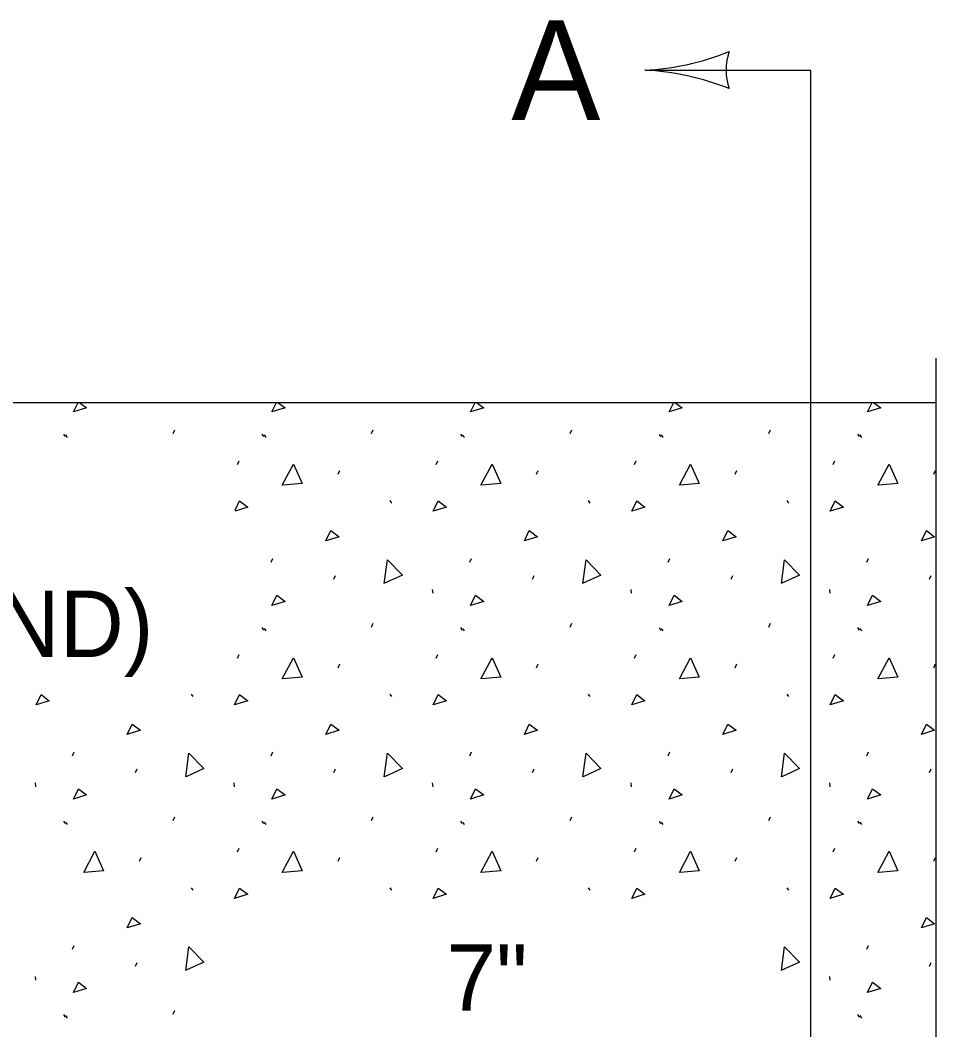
# Model space of a CAD drawing. Extents: x 49991.4 to 50021, y 49987.6 to 50011.4.
# Drawn here: x 50006.829 to 50007.655, y 49991.76 to 49992.672 of the extents above; entities that cross this region are included whole.
import ezdxf

# ---------------------------------------------------------------- set-up
doc = ezdxf.new("R2010")
doc.units = 0
for name, color, linetype in [('Level 1', 7, 'Continuous'), ('Level 2', 7, 'Continuous'), ('Level 3', 7, 'Continuous'), ('Level 6', 7, 'Continuous')]:
    doc.layers.add(name, color=color, linetype=linetype)

msp = doc.modelspace()

# ---------------------------------------------------------------- linework, layer by layer
at = {"layer": 'Level 1'}
for p, q in [((50005.32721, 49992.32693), (50007.65502, 49992.32693)), ((50006.87687, 49992.31824), (50006.88104, 49992.32693)), ((50007.05602, 49992.31824), (50007.0602, 49992.32693)), ((50007.23518, 49992.31824), (50007.23935, 49992.32693)), ((50007.41434, 49992.31824), (50007.41851, 49992.32693)), ((50007.5935, 49992.31824), (50007.59767, 49992.32693)), ((50006.86778, 49992.29835), (50006.86927, 49992.29611)), ((50006.86977, 49992.29749), (50006.87127, 49992.29526)), ((50006.96675, 49992.29885), (50006.96824, 49992.3022)), ((50007.04694, 49992.29835), (50007.04843, 49992.29611)), ((50007.04893, 49992.29749), (50007.05043, 49992.29526)), ((50007.14591, 49992.29885), (50007.1474, 49992.3022)), ((50007.2261, 49992.29835), (50007.22759, 49992.29611)), ((50007.22809, 49992.29749), (50007.22958, 49992.29526)), ((50007.32507, 49992.29885), (50007.32656, 49992.3022)), ((50007.40526, 49992.29835), (50007.40675, 49992.29611)), ((50007.40725, 49992.29749), (50007.40874, 49992.29526)), ((50007.50423, 49992.29885), (50007.50572, 49992.3022)), ((50007.58442, 49992.29835), (50007.58591, 49992.29611)), ((50007.58641, 49992.29749), (50007.5879, 49992.29526)), ((50007.02493, 49992.2707), (50007.02642, 49992.27405)), ((50007.20409, 49992.2707), (50007.20558, 49992.27405)), ((50007.38325, 49992.2707), (50007.38474, 49992.27405)), ((50007.56241, 49992.2707), (50007.5639, 49992.27405)), ((50007.1157, 49992.26212), (50007.11719, 49992.26548)), ((50007.29486, 49992.26212), (50007.29635, 49992.26548)), ((50007.47401, 49992.26212), (50007.47551, 49992.26548)), ((50007.65317, 49992.26212), (50007.65467, 49992.26548)), ((50007.02276, 49992.22947), (50007.0268, 49992.23788)), ((50007.03426, 49992.23228), (50007.02276, 49992.22869)), ((50007.0268, 49992.23788), (50007.03426, 49992.23228)), ((50007.16232, 49992.23825), (50007.16381, 49992.23601)), ((50007.20148, 49992.22855), (50007.20596, 49992.23788)), ((50007.21342, 49992.23228), (50007.20148, 49992.22855)), ((50007.20596, 49992.23788), (50007.21342, 49992.23228)), ((50007.34148, 49992.23825), (50007.34297, 49992.23601)), ((50007.38064, 49992.22855), (50007.38512, 49992.23788)), ((50007.39257, 49992.23228), (50007.38064, 49992.22855)), ((50007.38512, 49992.23788), (50007.39257, 49992.23228)), ((50007.52064, 49992.23825), (50007.52213, 49992.23601)), ((50007.5598, 49992.22855), (50007.56427, 49992.23788)), ((50007.57173, 49992.23228), (50007.5598, 49992.22855)), ((50007.56427, 49992.23788), (50007.57173, 49992.23228)), ((50007.05528, 49992.18268), (50007.05677, 49992.18604)), ((50007.23444, 49992.18268), (50007.23593, 49992.18604)), ((50007.41359, 49992.18268), (50007.41509, 49992.18604)), ((50007.59275, 49992.18268), (50007.59425, 49992.18604)), ((50007.11197, 49992.16739), (50007.11346, 49992.17074)), ((50007.29113, 49992.16739), (50007.29262, 49992.17074)), ((50007.47029, 49992.16739), (50007.47178, 49992.17074)), ((50007.64944, 49992.16739), (50007.65094, 49992.17074)), ((50007.20064, 49992.15802), (50007.20102, 49992.15466)), ((50007.3798, 49992.15802), (50007.38018, 49992.15466)), ((50007.55896, 49992.15802), (50007.55933, 49992.15466)), ((50007.04694, 49992.12362), (50007.04843, 49992.12139)), ((50007.04893, 49992.12277), (50007.05043, 49992.12054)), ((50007.14591, 49992.12412), (50007.1474, 49992.12748)), ((50007.2261, 49992.12362), (50007.22759, 49992.12139)), ((50007.22809, 49992.12277), (50007.22958, 49992.12054)), ((50007.32507, 49992.12412), (50007.32656, 49992.12748)), ((50007.40526, 49992.12362), (50007.40675, 49992.12139)), ((50007.40725, 49992.12277), (50007.40874, 49992.12054)), ((50007.50423, 49992.12412), (50007.50572, 49992.12748)), ((50007.58442, 49992.12362), (50007.58591, 49992.12139)), ((50007.58641, 49992.12277), (50007.5879, 49992.12054)), ((50007.02493, 49992.09598), (50007.02642, 49992.09933)), ((50007.20409, 49992.09598), (50007.20558, 49992.09933)), ((50007.38325, 49992.09598), (50007.38474, 49992.09933)), ((50007.56241, 49992.09598), (50007.5639, 49992.09933)), ((50007.1157, 49992.0874), (50007.11719, 49992.09076)), ((50007.29486, 49992.0874), (50007.29635, 49992.09076)), ((50007.47401, 49992.0874), (50007.47551, 49992.09076)), ((50007.65317, 49992.0874), (50007.65467, 49992.09076)), ((50006.84316, 49992.05383), (50006.84764, 49992.06316)), ((50006.8551, 49992.05756), (50006.84316, 49992.05383)), ((50006.84764, 49992.06316), (50006.8551, 49992.05756)), ((50006.98316, 49992.06353), (50006.98465, 49992.06129)), ((50007.02232, 49992.05383), (50007.0268, 49992.06316)), ((50007.03426, 49992.05756), (50007.02232, 49992.05383)), ((50007.0268, 49992.06316), (50007.03426, 49992.05756)), ((50007.16232, 49992.06353), (50007.16381, 49992.06129)), ((50007.20148, 49992.05383), (50007.20596, 49992.06316)), ((50007.21342, 49992.05756), (50007.20148, 49992.05383)), ((50007.20596, 49992.06316), (50007.21342, 49992.05756)), ((50007.34148, 49992.06353), (50007.34297, 49992.06129)), ((50007.38064, 49992.05383), (50007.38512, 49992.06316)), ((50007.39257, 49992.05756), (50007.38064, 49992.05383)), ((50007.38512, 49992.06316), (50007.39257, 49992.05756)), ((50007.52064, 49992.06353), (50007.52213, 49992.06129)), ((50007.5598, 49992.05383), (50007.56427, 49992.06316)), ((50007.57173, 49992.05756), (50007.5598, 49992.05383)), ((50007.56427, 49992.06316), (50007.57173, 49992.05756)), ((50006.87612, 49992.00796), (50006.87761, 49992.01131)), ((50007.05528, 49992.00796), (50007.05677, 49992.01131)), ((50007.23444, 49992.00796), (50007.23593, 49992.01131)), ((50007.41359, 49992.00796), (50007.41509, 49992.01131)), ((50007.59275, 49992.00796), (50007.59425, 49992.01131)), ((50006.93281, 49991.99266), (50006.9343, 49991.99602)), ((50007.11197, 49991.99266), (50007.11346, 49991.99602)), ((50007.29113, 49991.99266), (50007.29262, 49991.99602)), ((50007.47029, 49991.99266), (50007.47178, 49991.99602)), ((50007.64944, 49991.99266), (50007.65094, 49991.99602)), ((50006.84232, 49991.9833), (50006.8427, 49991.97994)), ((50007.02148, 49991.9833), (50007.02186, 49991.97994)), ((50007.20064, 49991.9833), (50007.20102, 49991.97994)), ((50007.3798, 49991.9833), (50007.38018, 49991.97994)), ((50007.55896, 49991.9833), (50007.55933, 49991.97994)), ((50006.86778, 49991.9489), (50006.86927, 49991.94666)), ((50006.86977, 49991.94805), (50006.87127, 49991.94581)), ((50006.96675, 49991.9494), (50006.96824, 49991.95276)), ((50007.04694, 49991.9489), (50007.04843, 49991.94666)), ((50007.04893, 49991.94805), (50007.05043, 49991.94581)), ((50007.14591, 49991.9494), (50007.1474, 49991.95276)), ((50007.2261, 49991.9489), (50007.22759, 49991.94666)), ((50007.22809, 49991.94805), (50007.22958, 49991.94581)), ((50007.32507, 49991.9494), (50007.32656, 49991.95276)), ((50007.40526, 49991.9489), (50007.40675, 49991.94666)), ((50007.40725, 49991.94805), (50007.40874, 49991.94581)), ((50007.50423, 49991.9494), (50007.50572, 49991.95276)), ((50007.58442, 49991.9489), (50007.58591, 49991.94666)), ((50007.58641, 49991.94805), (50007.5879, 49991.94581)), ((50007.02493, 49991.92125), (50007.02642, 49991.92461)), ((50007.20409, 49991.92125), (50007.20558, 49991.92461)), ((50007.38325, 49991.92125), (50007.38474, 49991.92461)), ((50007.56241, 49991.92125), (50007.5639, 49991.92461)), ((50006.93654, 49991.91268), (50006.93803, 49991.91603)), ((50007.1157, 49991.91268), (50007.11719, 49991.91603)), ((50007.29486, 49991.91268), (50007.29635, 49991.91603)), ((50007.47401, 49991.91268), (50007.47551, 49991.91603)), ((50007.65317, 49991.91268), (50007.65467, 49991.91603)), ((50006.98316, 49991.88881), (50006.98465, 49991.88657)), ((50007.02232, 49991.87911), (50007.0268, 49991.88843)), ((50007.0268, 49991.88843), (50007.03426, 49991.88284)), ((50007.16232, 49991.88881), (50007.16381, 49991.88657)), ((50007.20148, 49991.87911), (50007.20596, 49991.88843)), ((50007.20596, 49991.88843), (50007.21342, 49991.88284)), ((50007.34148, 49991.88881), (50007.34297, 49991.88657)), ((50007.38064, 49991.87911), (50007.38512, 49991.88843)), ((50007.38512, 49991.88843), (50007.39257, 49991.88284)), ((50007.52064, 49991.88881), (50007.52213, 49991.88657)), ((50007.5598, 49991.87911), (50007.56427, 49991.88843)), ((50007.56427, 49991.88843), (50007.57173, 49991.88284)), ((50007.03426, 49991.88284), (50007.02232, 49991.87911)), ((50007.21342, 49991.88284), (50007.20148, 49991.87911)), ((50007.39257, 49991.88284), (50007.38064, 49991.87911)), ((50007.57173, 49991.88284), (50007.5598, 49991.87911)), ((50006.87612, 49991.83324), (50006.87761, 49991.83659)), ((50007.59275, 49991.83324), (50007.59425, 49991.83659)), ((50006.93281, 49991.81794), (50006.9343, 49991.8213)), ((50007.64944, 49991.81794), (50007.65094, 49991.8213)), ((50006.84232, 49991.80858), (50006.8427, 49991.80522)), ((50007.55896, 49991.80858), (50007.55933, 49991.80522)), ((50006.86778, 49991.77418), (50006.86927, 49991.77194)), ((50006.96675, 49991.77468), (50006.96824, 49991.77804)), ((50007.58442, 49991.77418), (50007.58591, 49991.77194)), ((50006.86977, 49991.77333), (50006.87127, 49991.77109)), ((50007.58641, 49991.77333), (50007.5879, 49991.77109))]:
    msp.add_line(p, q, dxfattribs=at)
for points in [[(50006.88219, 49992.32693), (50006.8888, 49992.32197), (50006.87687, 49992.31824)], [(50007.06134, 49992.32693), (50007.06796, 49992.32197), (50007.05602, 49992.31824)], [(50007.2405, 49992.32693), (50007.24712, 49992.32197), (50007.23518, 49992.31824)], [(50007.41966, 49992.32693), (50007.42628, 49992.32197), (50007.41434, 49992.31824)], [(50007.59882, 49992.32693), (50007.60543, 49992.32197), (50007.5935, 49992.31824)], [(50007.06535, 49992.25205), (50007.07542, 49992.27107), (50007.08325, 49992.25354), (50007.06572, 49992.25205)], [(50007.24451, 49992.25205), (50007.25458, 49992.27107), (50007.26241, 49992.25354), (50007.24488, 49992.25205)], [(50007.42367, 49992.25205), (50007.43373, 49992.27107), (50007.44157, 49992.25354), (50007.42404, 49992.25205)], [(50007.60282, 49992.25205), (50007.61289, 49992.27107), (50007.62073, 49992.25354), (50007.6032, 49992.25205)], [(50007.10458, 49992.20189), (50007.10906, 49992.21122), (50007.11652, 49992.20562), (50007.10458, 49992.20189)], [(50007.28374, 49992.20189), (50007.28822, 49992.21122), (50007.29568, 49992.20562), (50007.28374, 49992.20189)], [(50007.4629, 49992.20189), (50007.46737, 49992.21122), (50007.47483, 49992.20562), (50007.4629, 49992.20189)], [(50007.64206, 49992.20189), (50007.64653, 49992.21122), (50007.65399, 49992.20562), (50007.64206, 49992.20189)], [(50007.15734, 49992.16353), (50007.1603, 49992.18484), (50007.17366, 49992.17105), (50007.15769, 49992.16365)], [(50007.3365, 49992.16353), (50007.33946, 49992.18484), (50007.35281, 49992.17105), (50007.33685, 49992.16365)], [(50007.51566, 49992.16353), (50007.51862, 49992.18484), (50007.53197, 49992.17105), (50007.51601, 49992.16365)], [(50007.05602, 49992.14352), (50007.0605, 49992.15284), (50007.06796, 49992.14725), (50007.05602, 49992.14352)], [(50007.23518, 49992.14352), (50007.23966, 49992.15284), (50007.24712, 49992.14725), (50007.23518, 49992.14352)], [(50007.41434, 49992.14352), (50007.41882, 49992.15284), (50007.42628, 49992.14725), (50007.41434, 49992.14352)], [(50007.5935, 49992.14352), (50007.59798, 49992.15284), (50007.60543, 49992.14725), (50007.5935, 49992.14352)], [(50007.06535, 49992.07733), (50007.07542, 49992.09635), (50007.08325, 49992.07882), (50007.06572, 49992.07733)], [(50007.24451, 49992.07733), (50007.25458, 49992.09635), (50007.26241, 49992.07882), (50007.24488, 49992.07733)], [(50007.42367, 49992.07733), (50007.43373, 49992.09635), (50007.44157, 49992.07882), (50007.42404, 49992.07733)], [(50007.60282, 49992.07733), (50007.61289, 49992.09635), (50007.62073, 49992.07882), (50007.6032, 49992.07733)], [(50006.92542, 49992.02717), (50006.9299, 49992.0365), (50006.93736, 49992.0309), (50006.92542, 49992.02717)], [(50007.10458, 49992.02717), (50007.10906, 49992.0365), (50007.11652, 49992.0309), (50007.10458, 49992.02717)], [(50007.28374, 49992.02717), (50007.28822, 49992.0365), (50007.29568, 49992.0309), (50007.28374, 49992.02717)], [(50007.4629, 49992.02717), (50007.46737, 49992.0365), (50007.47483, 49992.0309), (50007.4629, 49992.02717)], [(50007.64206, 49992.02717), (50007.64653, 49992.0365), (50007.65399, 49992.0309), (50007.64206, 49992.02717)], [(50006.97819, 49991.98881), (50006.98114, 49992.01012), (50006.9945, 49991.99633), (50006.97853, 49991.98893)], [(50007.15734, 49991.98881), (50007.1603, 49992.01012), (50007.17366, 49991.99633), (50007.15769, 49991.98893)], [(50007.3365, 49991.98881), (50007.33946, 49992.01012), (50007.35281, 49991.99633), (50007.33685, 49991.98893)], [(50007.51566, 49991.98881), (50007.51862, 49992.01012), (50007.53197, 49991.99633), (50007.51601, 49991.98893)], [(50006.87687, 49991.9688), (50006.88134, 49991.97812), (50006.8888, 49991.97253), (50006.87687, 49991.9688)], [(50007.05602, 49991.9688), (50007.0605, 49991.97812), (50007.06796, 49991.97253), (50007.05602, 49991.9688)], [(50007.23518, 49991.9688), (50007.23966, 49991.97812), (50007.24712, 49991.97253), (50007.23518, 49991.9688)], [(50007.41434, 49991.9688), (50007.41882, 49991.97812), (50007.42628, 49991.97253), (50007.41434, 49991.9688)], [(50007.5935, 49991.9688), (50007.59798, 49991.97812), (50007.60543, 49991.97253), (50007.5935, 49991.9688)], [(50006.88619, 49991.90261), (50006.89626, 49991.92163), (50006.90409, 49991.9041), (50006.88656, 49991.90261)], [(50007.06535, 49991.90261), (50007.07542, 49991.92163), (50007.08325, 49991.9041), (50007.06572, 49991.90261)], [(50007.24451, 49991.90261), (50007.25458, 49991.92163), (50007.26241, 49991.9041), (50007.24488, 49991.90261)], [(50007.42367, 49991.90261), (50007.43373, 49991.92163), (50007.44157, 49991.9041), (50007.42404, 49991.90261)], [(50007.60282, 49991.90261), (50007.61289, 49991.92163), (50007.62073, 49991.9041), (50007.6032, 49991.90261)], [(50006.92542, 49991.85245), (50006.9299, 49991.86177), (50006.93736, 49991.85618), (50006.92542, 49991.85245)], [(50007.64206, 49991.85245), (50007.64653, 49991.86177), (50007.65399, 49991.85618), (50007.64206, 49991.85245)], [(50006.97819, 49991.81408), (50006.98114, 49991.8354), (50006.9945, 49991.82161), (50006.97853, 49991.81421)], [(50007.51566, 49991.81408), (50007.51862, 49991.8354), (50007.53197, 49991.82161), (50007.51601, 49991.81421)], [(50006.87687, 49991.79407), (50006.88134, 49991.8034), (50006.8888, 49991.7978), (50006.87687, 49991.79407)], [(50007.5935, 49991.79407), (50007.59798, 49991.8034), (50007.60543, 49991.7978), (50007.5935, 49991.79407)]]:
    msp.add_lwpolyline(points, dxfattribs=at)
at = {"layer": 'Level 3'}
for p in [(50007.39234, 49992.62693), (50007.54234, 49990.39469)]:
    msp.add_line(p, (50007.54234, 49992.62693), dxfattribs=at)
for centre, radius, start, end in [((50007.38318, 49992.84906), 0.22232, 272.36048, 292.54399), ((50007.52055, 49992.62693), 0.05477, 162.13882, 197.86118), ((50007.38085, 49992.39422), 0.233, 67.92284, 87.17269)]:
    msp.add_arc(centre, radius, start, end, dxfattribs=at)
at = {"layer": 'Level 6'}
msp.add_line((50007.65502, 49992.36693), (50007.65502, 49991.5129), dxfattribs=at)

# ---------------------------------------------------------------- texts
at = {"layer": 'Level 2'}
for s, height, p in [('A', 0.09, (50007.27207, 49992.58193)), ('(SQUARE OR ROUND)', 0.06, (50006.09765, 49992.09701)), ('7" ', 0.06, (50007.21357, 49991.77769))]:
    msp.add_text(s, height=height, dxfattribs=at).set_placement(p)

doc.saveas('drawing.dxf')
